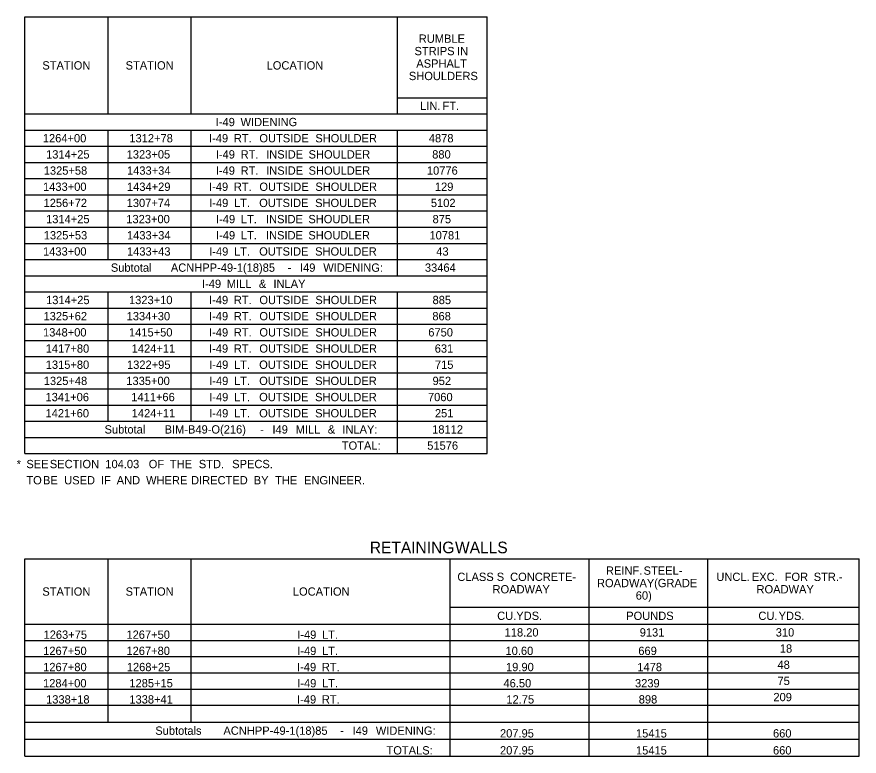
# Model space of a CAD drawing. Extents: x 1226589 to 1228130, y 151309 to 152305.
# Drawn here: x 1227262 to 1227770, y 151395 to 151841 of the extents above; entities that cross this region are included whole.
import ezdxf

# ---------------------------------------------------------------- set-up
doc = ezdxf.new("R2010")
doc.units = 0
doc.layers.add('R_Dimension', color=7, linetype='Continuous')

msp = doc.modelspace()

# ---------------------------------------------------------------- linework, layer by layer
at = {"layer": 'R_Dimension'}
for p, q in [((1227266.8, 151840.88), (1227545.65, 151840.88)), ((1227266.8, 151577.63), (1227266.8, 151840.88)), ((1227317.01, 151782.38), (1227317.01, 151840.88)), ((1227367.23, 151782.38), (1227367.23, 151840.88)), ((1227491.54, 151782.38), (1227491.54, 151840.88)), ((1227545.65, 151577.63), (1227545.65, 151840.88)), ((1227491.54, 151792.13), (1227545.65, 151792.13)), ((1227266.8, 151782.38), (1227545.65, 151782.38)), ((1227266.8, 151772.63), (1227545.65, 151772.63)), ((1227317.01, 151694.63), (1227317.01, 151772.63)), ((1227367.23, 151694.63), (1227367.23, 151772.63)), ((1227491.54, 151684.88), (1227491.54, 151772.63)), ((1227266.8, 151762.88), (1227545.65, 151762.88)), ((1227266.8, 151753.13), (1227545.65, 151753.13)), ((1227266.8, 151743.38), (1227545.65, 151743.38)), ((1227266.8, 151733.63), (1227545.65, 151733.63)), ((1227266.8, 151723.88), (1227545.65, 151723.88)), ((1227266.8, 151714.13), (1227545.65, 151714.13)), ((1227266.8, 151704.38), (1227545.65, 151704.38)), ((1227266.8, 151694.63), (1227545.65, 151694.63)), ((1227266.8, 151684.88), (1227545.65, 151684.88)), ((1227266.8, 151675.13), (1227545.65, 151675.13)), ((1227317.01, 151597.13), (1227317.01, 151675.13)), ((1227367.23, 151597.13), (1227367.23, 151675.13)), ((1227491.54, 151577.63), (1227491.54, 151675.13)), ((1227266.8, 151665.38), (1227545.65, 151665.38)), ((1227266.8, 151655.63), (1227545.65, 151655.63)), ((1227266.8, 151645.88), (1227545.65, 151645.88)), ((1227266.8, 151636.13), (1227545.65, 151636.13)), ((1227266.8, 151626.38), (1227545.65, 151626.38)), ((1227266.8, 151616.63), (1227545.65, 151616.63)), ((1227266.8, 151606.88), (1227545.65, 151606.88)), ((1227266.8, 151597.13), (1227545.65, 151597.13)), ((1227266.8, 151587.38), (1227545.65, 151587.38)), ((1227266.8, 151577.63), (1227545.65, 151577.63)), ((1227266.8, 151514.29), (1227769.9, 151514.29)), ((1227266.8, 151395.34), (1227266.8, 151514.29)), ((1227317.01, 151415.81), (1227317.01, 151514.29)), ((1227367.23, 151415.81), (1227367.23, 151514.29)), ((1227523.23, 151395.34), (1227523.23, 151514.29)), ((1227607.08, 151395.34), (1227607.08, 151514.29)), ((1227678.74, 151395.34), (1227678.74, 151514.29)), ((1227769.9, 151395.34), (1227769.9, 151514.29)), ((1227523.23, 151485.04), (1227769.9, 151485.04)), ((1227266.8, 151474.8), (1227769.9, 151474.8)), ((1227266.8, 151465.05), (1227769.9, 151465.05)), ((1227266.8, 151455.3), (1227769.9, 151455.3)), ((1227266.8, 151445.55), (1227769.9, 151445.55)), ((1227266.8, 151435.8), (1227769.9, 151435.8)), ((1227266.8, 151426.05), (1227769.9, 151426.05)), ((1227266.8, 151415.81), (1227769.9, 151415.81)), ((1227266.8, 151405.58), (1227769.9, 151405.58)), ((1227266.8, 151395.34), (1227769.9, 151395.34))]:
    msp.add_line(p, q, dxfattribs=at)

# ---------------------------------------------------------------- texts
for s, height, p in [(' RUMBLE', 5, (1227502.51, 151825.25)), ('STRIPS', 5, (1227501.82, 151817.75)), (' IN', 5, (1227525.6, 151817.75)), ('STATION', 5, (1227277.4, 151809.13)), ('STATION', 5, (1227327.61, 151809.13)), ('LOCATION', 5, (1227412.63, 151809.13)), ('ASPHALT', 5, (1227502.87, 151810.25)), ('SHOULDERS', 5, (1227498.4, 151802.75)), ('LIN.', 5, (1227505.19, 151784.75)), (' FT.', 5, (1227516.84, 151784.75)), ('I-49', 5, (1227381.95, 151775)), (' WIDENING', 5, (1227395.06, 151775)), ('1264+00', 5, (1227277.71, 151765.25)), ('1312+78', 5, (1227329.88, 151765.25)), ('I-49', 5, (1227377.91, 151765.25)), (' RT.', 5, (1227391.02, 151765.25)), (' OUTSIDE', 5, (1227406.41, 151765.25)), (' SHOULDER', 5, (1227440.15, 151765.25)), ('4878', 5, (1227510.44, 151765.25)), ('1314+25', 5, (1227279.66, 151755.5)), ('1323+05', 5, (1227328.26, 151755.5)), ('I-49', 5, (1227382, 151755.5)), (' RT.', 5, (1227395.11, 151755.5)), (' INSIDE', 5, (1227410.5, 151755.5)), (' SHOULDER', 5, (1227436.06, 151755.5)), ('880', 5, (1227512.47, 151755.5)), ('1325+58', 5, (1227278.25, 151745.75)), ('1433+34', 5, (1227328.46, 151745.75)), ('I-49', 5, (1227382, 151745.75)), (' RT.', 5, (1227395.11, 151745.75)), (' INSIDE', 5, (1227410.5, 151745.75)), (' SHOULDER', 5, (1227436.06, 151745.75)), ('10776', 5, (1227509.28, 151745.75)), ('1433+00', 5, (1227277.83, 151736)), ('1434+29', 5, (1227328.44, 151736)), ('I-49', 5, (1227377.91, 151736)), (' RT.', 5, (1227391.02, 151736)), (' OUTSIDE', 5, (1227406.41, 151736)), (' SHOULDER', 5, (1227440.15, 151736)), ('129', 5, (1227514.09, 151736)), ('1256+72', 5, (1227278.13, 151726.25)), ('1307+74', 5, (1227328.26, 151726.25)), ('I-49', 5, (1227378.02, 151726.25)), (' LT.', 5, (1227391.13, 151726.25)), (' OUTSIDE', 5, (1227406.29, 151726.25)), (' SHOULDER', 5, (1227440.03, 151726.25)), ('5102', 5, (1227511.67, 151726.25)), ('1314+25', 5, (1227279.66, 151716.5)), ('1323+00', 5, (1227328.04, 151716.5)), ('I-49', 5, (1227382.12, 151716.5)), (' LT.', 5, (1227395.23, 151716.5)), (' INSIDE', 5, (1227410.39, 151716.5)), (' SHOUDLER', 5, (1227435.94, 151716.5)), ('875', 5, (1227512.69, 151716.5)), ('1325+53', 5, (1227278.25, 151706.75)), ('1433+34', 5, (1227328.46, 151706.75)), ('I-49', 5, (1227382.12, 151706.75)), (' LT.', 5, (1227395.23, 151706.75)), (' INSIDE', 5, (1227410.39, 151706.75)), (' SHOUDLER', 5, (1227435.94, 151706.75)), ('10781', 5, (1227510.84, 151706.75)), ('1433+00', 5, (1227277.83, 151697)), ('1433+43', 5, (1227328.46, 151697)), ('I-49', 5, (1227378.02, 151697)), (' LT.', 5, (1227391.13, 151697)), (' OUTSIDE', 5, (1227406.29, 151697)), (' SHOULDER', 5, (1227440.03, 151697)), ('43', 5, (1227514.93, 151697)), ('Subtotal', 5, (1227318.71, 151687.25)), (' ACNHPP-49-1(18)85', 5, (1227353.04, 151687.25)), (' I49', 5, (1227430.91, 151687.25)), (' WIDENING:', 5, (1227444.93, 151687.25)), ('33464', 5, (1227508.08, 151687.25)), (' -', 5, (1227423.47, 151687.25)), ('I-49', 5, (1227373.67, 151677.5)), (' MILL', 5, (1227386.78, 151677.5)), (' &', 5, (1227406.11, 151677.5)), (' INLAY', 5, (1227414.89, 151677.5)), ('1314+25', 5, (1227279.66, 151667.75)), ('1323+10', 5, (1227329.66, 151667.75)), ('I-49', 5, (1227377.91, 151667.75)), (' RT.', 5, (1227391.02, 151667.75)), (' OUTSIDE', 5, (1227406.41, 151667.75)), (' SHOULDER', 5, (1227440.15, 151667.75)), ('885', 5, (1227512.69, 151667.75)), ('1325+62', 5, (1227278.13, 151658)), ('1334+30', 5, (1227328.24, 151658)), ('I-49', 5, (1227377.91, 151658)), (' RT.', 5, (1227391.02, 151658)), (' OUTSIDE', 5, (1227406.41, 151658)), (' SHOULDER', 5, (1227440.15, 151658)), ('868', 5, (1227512.57, 151658)), ('1348+00', 5, (1227277.83, 151648.25)), ('1415+50', 5, (1227329.66, 151648.25)), ('I-49', 5, (1227377.91, 151648.25)), (' RT.', 5, (1227391.02, 151648.25)), (' OUTSIDE', 5, (1227406.41, 151648.25)), (' SHOULDER', 5, (1227440.15, 151648.25)), ('6750', 5, (1227510.11, 151648.25)), ('1417+80', 5, (1227279.45, 151638.5)), ('1424+11', 5, (1227331.29, 151638.5)), ('I-49', 5, (1227377.91, 151638.5)), (' RT.', 5, (1227391.02, 151638.5)), (' OUTSIDE', 5, (1227406.41, 151638.5)), (' SHOULDER', 5, (1227440.15, 151638.5)), ('631', 5, (1227513.99, 151638.5)), ('1315+80', 5, (1227279.45, 151628.75)), ('1322+95', 5, (1227328.46, 151628.75)), ('I-49', 5, (1227378.02, 151628.75)), (' LT.', 5, (1227391.13, 151628.75)), (' OUTSIDE', 5, (1227406.29, 151628.75)), (' SHOULDER', 5, (1227440.03, 151628.75)), ('715', 5, (1227514.11, 151628.75)), ('1325+48', 5, (1227278.25, 151619)), ('1335+00', 5, (1227328.04, 151619)), ('I-49', 5, (1227378.02, 151619)), (' LT.', 5, (1227391.13, 151619)), (' OUTSIDE', 5, (1227406.29, 151619)), (' SHOULDER', 5, (1227440.03, 151619)), ('952', 5, (1227512.69, 151619)), ('1341+06', 5, (1227279.33, 151609.25)), ('1411+66', 5, (1227331.04, 151609.25)), ('I-49', 5, (1227378.02, 151609.25)), (' LT.', 5, (1227391.13, 151609.25)), (' OUTSIDE', 5, (1227406.29, 151609.25)), (' SHOULDER', 5, (1227440.03, 151609.25)), ('7060', 5, (1227509.91, 151609.25)), ('1421+60', 5, (1227279.33, 151599.5)), ('1424+11', 5, (1227331.29, 151599.5)), ('I-49', 5, (1227378.02, 151599.5)), (' LT.', 5, (1227391.13, 151599.5)), (' OUTSIDE', 5, (1227406.29, 151599.5)), (' SHOULDER', 5, (1227440.03, 151599.5)), ('251', 5, (1227514.11, 151599.5)), ('Subtotal', 5, (1227314.93, 151589.75)), (' BIM-B49-O(216)', 5, (1227349.26, 151589.75)), (' I49', 5, (1227414.3, 151589.75)), (' MILL', 5, (1227428.31, 151589.75)), (' &', 5, (1227447.65, 151589.75)), (' INLAY:', 5, (1227456.42, 151589.75)), ('18112', 5, (1227512.45, 151589.75)), (' -', 5, (1227406.86, 151589.75)), ('TOTAL:', 5, (1227457.96, 151580)), ('51576', 5, (1227509.48, 151580)), ('*', 5, (1227261.93, 151568.88)), ('SEE', 5, (1227267.78, 151568.88)), (' SECTION', 5, (1227280.06, 151568.88)), (' 104.03', 5, (1227313.52, 151568.88)), (' OF', 5, (1227339.7, 151568.88)), (' THE', 5, (1227352.46, 151568.88)), (' STD.', 5, (1227369.9, 151568.88)), (' SPECS.', 5, (1227390.02, 151568.88)), ('TO', 5, (1227267.78, 151559.13)), (' BE', 5, (1227275.93, 151559.13)), (' USED', 5, (1227288.72, 151559.13)), (' IF', 5, (1227310.85, 151559.13)), (' AND', 5, (1227320.37, 151559.13)), (' WHERE', 5, (1227338.09, 151559.13)), (' DIRECTED', 5, (1227365.22, 151559.13)), (' BY', 5, (1227403.01, 151559.13)), (' THE', 5, (1227415.89, 151559.13)), (' ENGINEER.', 5, (1227433.33, 151559.13)), ('RETAINING', 7, (1227474.86, 151517.61)), (' WALLS', 7, (1227523.64, 151517.61)), ('REINF.', 5, (1227617.22, 151504.66)), (' STEEL-', 5, (1227638.08, 151504.66)), ('CLASS', 5, (1227527.63, 151500.91)), (' S', 5, (1227549.52, 151500.91)), (' CONCRETE-', 5, (1227557.59, 151500.91)), ('ROADWAY', 5, (1227611.82, 151497.16)), (' (GRADE', 5, (1227644.42, 151497.16)), ('UNCL.', 5, (1227683.81, 151500.91)), (' EXC.', 5, (1227703.34, 151500.91)), (' FOR', 5, (1227723.14, 151500.91)), (' STR.-', 5, (1227740.62, 151500.91)), ('STATION', 5, (1227277.4, 151492.05)), ('STATION', 5, (1227327.61, 151492.05)), ('LOCATION', 5, (1227428.47, 151492.05)), ('ROADWAY', 5, (1227548.85, 151493.41)), ('ROADWAY', 5, (1227708.02, 151493.41)), ('60)', 5, (1227635.21, 151489.66)), ('CU.YDS.', 5, (1227551.65, 151477.42)), ('POUNDS', 5, (1227629.44, 151477.42)), ('CU.', 5, (1227709.14, 151477.42)), (' YDS.', 5, (1227719.46, 151477.42)), ('118.20', 5, (1227556.15, 151467.43)), ('9131', 5, (1227637.59, 151467.43)), ('310', 5, (1227719.61, 151467.43)), ('1263+75', 5, (1227278.13, 151466.05)), ('1267+50', 5, (1227328.12, 151466.05)), ('I-49', 5, (1227431.09, 151466.05)), (' LT.', 5, (1227444.2, 151466.05)), ('1267+50', 5, (1227277.91, 151456.3)), ('1267+80', 5, (1227328.12, 151456.3)), ('I-49', 5, (1227431.09, 151456.3)), (' LT.', 5, (1227444.2, 151456.3)), ('10.60', 5, (1227556.67, 151456.3)), ('669', 5, (1227636.75, 151456.3)), ('18', 5, (1227722.08, 151457.68)), ('1267+80', 5, (1227277.91, 151446.55)), ('1268+25', 5, (1227328.34, 151446.55)), ('I-49', 5, (1227430.97, 151446.55)), (' RT.', 5, (1227444.08, 151446.55)), ('19.90', 5, (1227556.98, 151446.55)), ('1478', 5, (1227636.17, 151446.55)), ('48', 5, (1227720.66, 151447.93)), ('1284+00', 5, (1227277.83, 151436.8)), ('1285+15', 5, (1227329.88, 151436.8)), ('I-49', 5, (1227431.09, 151436.8)), (' LT.', 5, (1227444.2, 151436.8)), ('46.50', 5, (1227555.45, 151436.8)), ('3239', 5, (1227634.74, 151436.8)), ('75', 5, (1227720.66, 151438.18)), ('1338+18', 5, (1227279.66, 151427.05)), ('1338+41', 5, (1227329.88, 151427.05)), ('I-49', 5, (1227430.97, 151427.05)), (' RT.', 5, (1227444.08, 151427.05)), ('12.75', 5, (1227557.2, 151427.05)), ('898', 5, (1227637, 151427.05)), ('209', 5, (1227718.2, 151428.43)), ('Subtotals', 5, (1227345.51, 151408.2)), (' ACNHPP-49-1(18)85', 5, (1227384.73, 151408.2)), (' I49', 5, (1227462.6, 151408.2)), (' WIDENING:', 5, (1227476.62, 151408.2)), ('207.95', 5, (1227553.34, 151406.58)), ('15415', 5, (1227635.35, 151406.58)), ('660', 5, (1227717.96, 151406.58)), (' -', 5, (1227455.16, 151408.2)), ('TOTALS:', 5, (1227484.92, 151396.34)), ('207.95', 5, (1227553.34, 151396.34)), ('15415', 5, (1227635.35, 151396.34)), ('660', 5, (1227717.96, 151396.34))]:
    msp.add_text(s, height=height, dxfattribs=at).set_placement(p)

doc.saveas('drawing.dxf')
